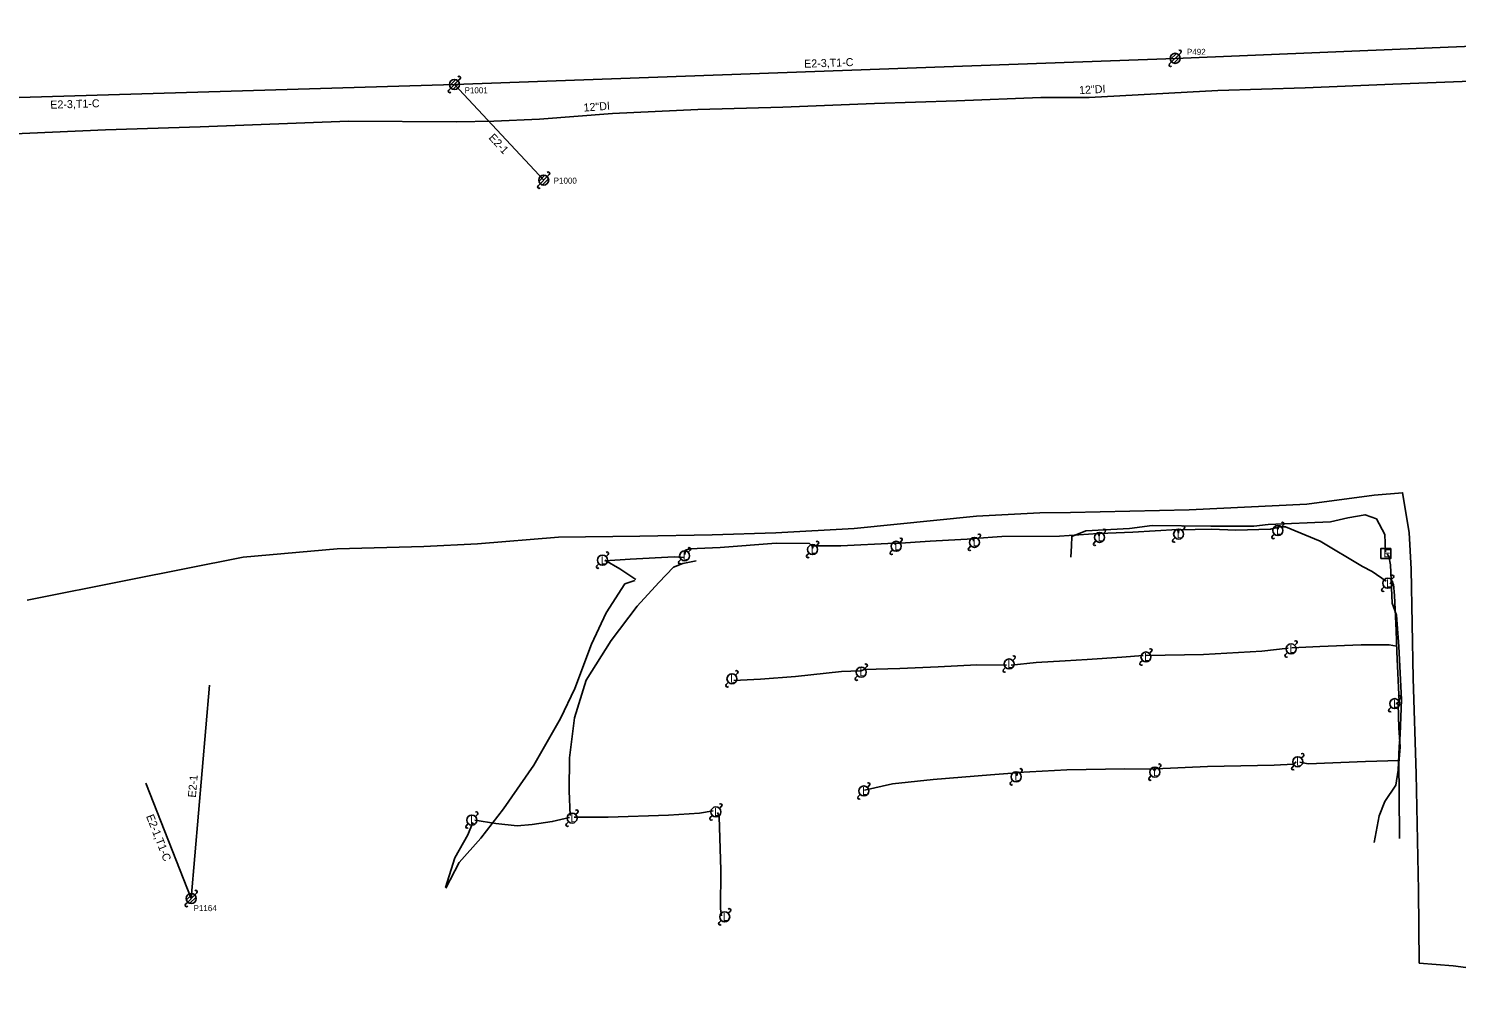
# Model space of a CAD drawing. Extents: x 1741604 to 1825760, y 1164229 to 1194908.
# Drawn here: x 1810361 to 1811075, y 1189784 to 1190261 of the extents above; entities that cross this region are included whole.
import ezdxf

# ---------------------------------------------------------------- set-up
doc = ezdxf.new("R2010")
doc.units = 0
for name, color, linetype in [('RD_EX_SU_Elec', 7, 'Continuous'), ('RD_EX_SU_Gas', 7, 'Continuous'), ('RD_EX_SU_H2O', 7, 'Continuous'), ('RD_EX_SU_Ovhd', 7, 'Continuous'), ('RD_EX_SU_Pole', 7, 'Continuous'), ('RD_EX_SU_TX_H2O', 7, 'Continuous'), ('RD_EX_SU_TX_Pole', 7, 'Continuous')]:
    doc.layers.add(name, color=color, linetype=linetype)

# ---------------------------------------------------------------- blocks, each defined once
blk = doc.blocks.new('SUE_EHH')
at = {"layer": 'RD_EX_SU_Elec'}
blk.add_lwpolyline([(2.5, 2.5), (-2.5, 2.5), (-2.5, -2.5), (2.5, -2.5)], close=True, dxfattribs=at)
blk.add_text('E', height=4, dxfattribs=at).set_placement((-1.24, -2))
blk = doc.blocks.new('SUE_PP')
at = {"layer": 'RD_EX_SU_Pole'}
for p, q in [((-2.41, -0.65), (0.65, 2.41)), ((-1.77, -1.77), (1.77, 1.77)), ((-0.65, -2.41), (2.41, 0.65)), ((1.77, 1.77), (2.83, 2.83)), ((-2.83, -2.83), (-1.77, -1.77))]:
    blk.add_line(p, q, dxfattribs=at)
blk.add_circle((0, 0), 2.5, dxfattribs=at)
for centre, start, end in [((2.3, 3.36), 315, 135), ((-2.3, -3.36), 135, 315)]:
    blk.add_arc(centre, 0.75, start, end, dxfattribs=at)

msp = doc.modelspace()

# ---------------------------------------------------------------- linework, layer by layer
at = {"layer": 'RD_EX_SU_Elec'}
for points in [[(1810882.41, 1189997.06), (1810882.6, 1190002.81), (1810882.79, 1190007.43), (1810889.9, 1190010.31), (1810911.74, 1190011.45), (1810922.99, 1190012.94), (1810952.38, 1190012.57), (1810973.77, 1190012.66), (1810980.97, 1190013.47), (1811012.08, 1190014.68), (1811020.74, 1190016.7), (1811029.44, 1190018.3), (1811035.04, 1190016.25), (1811039.36, 1190008.48), (1811039.58, 1189999.69)], [(1810833.73, 1190005.02), (1810834.03, 1190006.36), (1810847.79, 1190007.43), (1810876.65, 1190007.52), (1810896.07, 1190008.91), (1810896.52, 1190007.83)], [(1810896.57, 1190007.73), (1810896.72, 1190008.93), (1810913.32, 1190009.56), (1810935.67, 1190010.85), (1810936.1, 1190009.29)], [(1810936.21, 1190009.15), (1810936.37, 1190010.84), (1810952.6, 1190011.17), (1810964.74, 1190010.6), (1810982.14, 1190011.14), (1810985.36, 1190011.98), (1810985.69, 1190011.21)], [(1810985.78, 1190011.09), (1810986.08, 1190012.29), (1810989.7, 1190012.26), (1811006.91, 1190005.06), (1811028.2, 1189992.46), (1811032.96, 1189989.92), (1811039.97, 1189985.1)], [(1810689.38, 1189998.41), (1810689.68, 1190000.63), (1810691.68, 1190001.24), (1810707.07, 1190001.91), (1810735.1, 1190004.09), (1810751.67, 1190003.88), (1810753.03, 1190002.58), (1810753.21, 1190001.46)], [(1810753.2, 1190001.53), (1810753.49, 1190002.77), (1810767.39, 1190002.69), (1810794.23, 1190004.05), (1810794.71, 1190003.36)], [(1810794.68, 1190003.33), (1810794.77, 1190003.99), (1810812.01, 1190005.06), (1810833.53, 1190006.28), (1810833.69, 1190005.05)], [(1810632.17, 1189868.03), (1810631.62, 1189880.27), (1810631.82, 1189896.78), (1810634.23, 1189916.89), (1810640.01, 1189935.59), (1810652.51, 1189955.38), (1810665.66, 1189972.7), (1810676.35, 1189984.52), (1810683.7, 1189992.06), (1810688.45, 1189993.95), (1810695.02, 1189995.25)], [(1810649.4, 1189995.34), (1810662.04, 1189996.13), (1810684.1, 1189997.27), (1810688.66, 1189997.01)], [(1810649.5, 1189995.56), (1810656.92, 1189991.27), (1810664.99, 1189985.89)], [(1811033.97, 1189854.58), (1811036.39, 1189867.83), (1811039.22, 1189875.07), (1811044.81, 1189883.1), (1811045.89, 1189890.69), (1811046.4, 1189902.32), (1811046.89, 1189908.41), (1811047.67, 1189925.91), (1811046.34, 1189952.43), (1811045.11, 1189968.19), (1811043.03, 1189974.06), (1811042.09, 1189993.25), (1811041.27, 1189997.63), (1811040.39, 1189998.52)], [(1810569.96, 1189831.7), (1810576.53, 1189844.54), (1810587.41, 1189856.76), (1810598.7, 1189871.38), (1810614.01, 1189893.17), (1810627.25, 1189916.45), (1810634.46, 1189931.47), (1810642.82, 1189953.65), (1810650.1, 1189969.23), (1810659.48, 1189983.75), (1810664.39, 1189985.49)], [(1811041.79, 1189984.09), (1811043.67, 1189983.61), (1811044.05, 1189978), (1811045.02, 1189960.44), (1811045.24, 1189949.72), (1811046.45, 1189924.79), (1811044.89, 1189923.94)], [(1810919.94, 1189947.98), (1810948.66, 1189948.49), (1810977.79, 1189950.17), (1810991.03, 1189951.57)], [(1810992.78, 1189951.74), (1811006.88, 1189952.43), (1811027.4, 1189953.36), (1811041.44, 1189953.37), (1811045.18, 1189952.65)], [(1810777.62, 1189940.28), (1810779.09, 1189940.94), (1810796.85, 1189941.53), (1810816, 1189942.3), (1810835.36, 1189943.35), (1810850.26, 1189943.1)], [(1810852.6, 1189943.18), (1810865.04, 1189944.39), (1810879.54, 1189945.23), (1810890.47, 1189946.03), (1810907.79, 1189947.12), (1810918.52, 1189947.89)], [(1810713.88, 1189935.52), (1810727.23, 1189936.17), (1810744.67, 1189937.45), (1810767.73, 1189940.04), (1810776.98, 1189940.35)], [(1811044.79, 1189923.96), (1811045.98, 1189923.72), (1811046.3, 1189911.84), (1811046.92, 1189902.32), (1811046.36, 1189894.11), (1811046.45, 1189878.94), (1811046.66, 1189856.56)], [(1810924.21, 1189890.35), (1810924.62, 1189891.33), (1810950.58, 1189892.52), (1810983.93, 1189893.16), (1810993.65, 1189893.61), (1810994.99, 1189894.8)], [(1810996.74, 1189894.72), (1811001.02, 1189893.84), (1811029.56, 1189895.05), (1811046.45, 1189895.43)], [(1810779.27, 1189880.69), (1810793.14, 1189883.8), (1810813.55, 1189885.99), (1810842.2, 1189888.26), (1810855.13, 1189889.39), (1810855.27, 1189887.92)], [(1810855.32, 1189887.77), (1810855.68, 1189889.43), (1810880.3, 1189890.8), (1810909.26, 1189891.31), (1810923.86, 1189891.12), (1810924.01, 1189890.37)], [(1810569.7, 1189832.07), (1810574.42, 1189846.88), (1810581.01, 1189858.31), (1810583.43, 1189864.5)], [(1810584.48, 1189865.7), (1810594.86, 1189864.03), (1810605.53, 1189862.81), (1810613.03, 1189863.44), (1810623.12, 1189864.97), (1810631.84, 1189867.06)], [(1810634.12, 1189867.14), (1810651.15, 1189867.24), (1810681.2, 1189868.26), (1810696.71, 1189869.18), (1810703.59, 1189870.37)], [(1810707.76, 1189817.87), (1810707.2, 1189821.31), (1810707.42, 1189840.71), (1810706.54, 1189867.52), (1810705.68, 1189869.44)]]:
    msp.add_lwpolyline(points, dxfattribs=at)
at = {"layer": 'RD_EX_SU_Gas'}
for points in [[(1810734.82, 1190009.27), (1810773.98, 1190011.4), (1810835.13, 1190017.51), (1810866.87, 1190019.27), (1810882.2, 1190019.48), (1810941.55, 1190020.78), (1811000.3, 1190023.52), (1811033.9, 1190028.14), (1811048.12, 1190029.33), (1811051.53, 1190009.48), (1811052.43, 1189991.18), (1811053.52, 1189936.49), (1811054.97, 1189888.82), (1811056.1, 1189830.56), (1811056.46, 1189794.24), (1811073.37, 1189792.97), (1811131.67, 1189785.28), (1811150.31, 1189783.6)], [(1810360.73, 1189975.64), (1810410.81, 1189985.57), (1810468.67, 1189997.18), (1810515.69, 1190001.21), (1810558.98, 1190002.44), (1810585.76, 1190003.83), (1810626.31, 1190007.08), (1810666.92, 1190007.6), (1810703.04, 1190008.2), (1810734.82, 1190009.27)]]:
    msp.add_lwpolyline(points, dxfattribs=at)
at = {"layer": 'RD_EX_SU_H2O'}
for points in [[(1810575.17, 1190214.64), (1810594, 1190215), (1810616.7, 1190215.99), (1810653.22, 1190218.84), (1810695.85, 1190220.76), (1810738.35, 1190222.04), (1810784.17, 1190223.81), (1810825.15, 1190225.11), (1810867.29, 1190226.82), (1810891.53, 1190226.72), (1810955.86, 1190230.25), (1810999.49, 1190231.58), (1811043.25, 1190233.5), (1811086.58, 1190235.09)], [(1809591.04, 1190181.32), (1809610.39, 1190182.17), (1809696.97, 1190185.67), (1809786.87, 1190188.66), (1809883.54, 1190192.41), (1809933.92, 1190194.51), (1810049.07, 1190198.52), (1810146.27, 1190201.48), (1810237.73, 1190204.86), (1810335.34, 1190207.78), (1810399.91, 1190210.57), (1810447.22, 1190212.22), (1810521.22, 1190215.05), (1810575.17, 1190214.64)]]:
    msp.add_lwpolyline(points, dxfattribs=at)
at = {"layer": 'RD_EX_SU_Ovhd'}
for p, q in [((1810934.49, 1190246.37), (1811299.74, 1190261.25)), ((1810574.24, 1190233.31), (1810934.49, 1190246.37)), ((1810212.63, 1190222.37), (1810574.24, 1190233.31)), ((1810574.24, 1190233.31), (1810618.85, 1190185.51)), ((1810442.69, 1189826.54), (1810451.79, 1189933.09)), ((1810419.99, 1189884.17), (1810442.69, 1189826.54))]:
    msp.add_line(p, q, dxfattribs=at)
at = {"layer": 'RD_EX_SU_Pole'}
for p, q in [((1810931.66, 1190243.54), (1810932.72, 1190244.6)), ((1810932.07, 1190245.72), (1810935.13, 1190248.79)), ((1810932.72, 1190244.6), (1810936.25, 1190248.14)), ((1810933.84, 1190243.96), (1810936.9, 1190247.02)), ((1810936.25, 1190248.14), (1810937.31, 1190249.2)), ((1810571.83, 1190232.66), (1810574.89, 1190235.73)), ((1810576.01, 1190235.08), (1810577.07, 1190236.14)), ((1810571.41, 1190230.48), (1810572.47, 1190231.54)), ((1810572.47, 1190231.54), (1810576.01, 1190235.08)), ((1810573.59, 1190230.9), (1810576.65, 1190233.96)), ((1810616.43, 1190184.86), (1810619.49, 1190187.92)), ((1810617.08, 1190183.74), (1810620.61, 1190187.28)), ((1810618.2, 1190183.09), (1810621.26, 1190186.15)), ((1810620.61, 1190187.28), (1810621.67, 1190188.34)), ((1810616.02, 1190182.68), (1810617.08, 1190183.74)), ((1810835.92, 1190006.26), (1810836.98, 1190007.32)), ((1810898.46, 1190008.78), (1810899.52, 1190009.84)), ((1810933.39, 1190005.81), (1810934.45, 1190006.87)), ((1810937.98, 1190010.4), (1810939.04, 1190011.47)), ((1810983, 1190007.59), (1810984.06, 1190008.65)), ((1810987.6, 1190012.18), (1810988.66, 1190013.24)), ((1810691.09, 1189999.56), (1810692.15, 1190000.62)), ((1810755.03, 1190002.68), (1810756.09, 1190003.74)), ((1810792.23, 1189999.71), (1810793.29, 1190000.77)), ((1810796.82, 1190004.3), (1810797.88, 1190005.36)), ((1810831.32, 1190001.66), (1810832.38, 1190002.72)), ((1810893.86, 1190004.18), (1810894.92, 1190005.24)), ((1810645.42, 1189992.77), (1810646.48, 1189993.83)), ((1810650.02, 1189997.37), (1810651.08, 1189998.43)), ((1810686.49, 1189994.97), (1810687.55, 1189996.03)), ((1810750.44, 1189998.08), (1810751.5, 1189999.14)), ((1811042.5, 1189985.83), (1811043.56, 1189986.89)), ((1811037.91, 1189981.23), (1811038.97, 1189982.29)), ((1810921.66, 1189949), (1810922.72, 1189950.06)), ((1810994.2, 1189953.02), (1810995.26, 1189954.08)), ((1810853.27, 1189945.48), (1810854.33, 1189946.54)), ((1810917.06, 1189944.4), (1810918.12, 1189945.46)), ((1810989.6, 1189948.42), (1810990.66, 1189949.48)), ((1810714.74, 1189938.09), (1810715.8, 1189939.15)), ((1810774.75, 1189936.83), (1810775.81, 1189937.89)), ((1810779.35, 1189941.42), (1810780.41, 1189942.48)), ((1810848.67, 1189940.89), (1810849.73, 1189941.95)), ((1810710.15, 1189933.5), (1810711.21, 1189934.56)), ((1811041.38, 1189921.07), (1811042.44, 1189922.13)), ((1811045.98, 1189925.66), (1811047.04, 1189926.72)), ((1810992.94, 1189892.05), (1810994, 1189893.11)), ((1810997.54, 1189896.65), (1810998.6, 1189897.71)), ((1810852.18, 1189884.51), (1810853.24, 1189885.57)), ((1810856.77, 1189889.11), (1810857.83, 1189890.17)), ((1810921.5, 1189886.86), (1810922.56, 1189887.92)), ((1810926.09, 1189891.45), (1810927.15, 1189892.51)), ((1810776.05, 1189877.43), (1810777.11, 1189878.49)), ((1810780.64, 1189882.03), (1810781.7, 1189883.09)), ((1810706.71, 1189871.58), (1810707.77, 1189872.64)), ((1810584.7, 1189867.49), (1810585.76, 1189868.55)), ((1810630.22, 1189863.87), (1810631.28, 1189864.93)), ((1810634.81, 1189868.47), (1810635.88, 1189869.53)), ((1810702.12, 1189866.98), (1810703.18, 1189868.04)), ((1810580.1, 1189862.89), (1810581.16, 1189863.95)), ((1810706.49, 1189814.54), (1810707.55, 1189815.6)), ((1810711.08, 1189819.14), (1810712.15, 1189820.2))]:
    msp.add_line(p, q, dxfattribs=at)
for centre in [(1810934.49, 1190246.37), (1810574.24, 1190233.31), (1810618.85, 1190185.51), (1810834.15, 1190004.49), (1810896.69, 1190007.01), (1810936.22, 1190008.64), (1810985.83, 1190010.41), (1810689.32, 1189997.8), (1810753.26, 1190000.91), (1810795.05, 1190002.54), (1810648.25, 1189995.6), (1811040.74, 1189984.06), (1810919.89, 1189947.23), (1810992.43, 1189951.25), (1810851.5, 1189943.72), (1810712.98, 1189936.33), (1810777.58, 1189939.65), (1811044.21, 1189923.9), (1810995.77, 1189894.88), (1810855, 1189887.34), (1810924.33, 1189889.69), (1810778.88, 1189880.26), (1810704.95, 1189869.81), (1810582.93, 1189865.72), (1810633.05, 1189866.7), (1810709.32, 1189817.37)]:
    msp.add_circle(centre, 2.5, dxfattribs=at)
for centre, start, end in [((1810936.78, 1190249.73), 315, 135), ((1810932.19, 1190243.01), 135, 315), ((1810576.54, 1190236.67), 315, 135), ((1810571.94, 1190229.95), 135, 315), ((1810621.14, 1190188.87), 315, 135), ((1810616.55, 1190182.15), 135, 315), ((1810988.13, 1190013.77), 315, 135), ((1810836.45, 1190007.85), 315, 135), ((1810898.99, 1190010.37), 315, 135), ((1810938.51, 1190012), 315, 135), ((1810983.53, 1190007.06), 135, 315), ((1810650.55, 1189998.96), 315, 135), ((1810691.62, 1190001.15), 315, 135), ((1810755.56, 1190004.27), 315, 135), ((1810792.76, 1189999.18), 135, 315), ((1810797.35, 1190005.89), 315, 135), ((1810831.85, 1190001.13), 135, 315), ((1810894.39, 1190003.65), 135, 315), ((1810933.92, 1190005.28), 135, 315), ((1810645.95, 1189992.24), 135, 315), ((1810687.02, 1189994.44), 135, 315), ((1810750.97, 1189997.55), 135, 315), ((1811043.03, 1189987.42), 315, 135), ((1811038.44, 1189980.7), 135, 315), ((1810922.19, 1189950.59), 315, 135), ((1810994.73, 1189954.61), 315, 135), ((1810779.88, 1189943.01), 315, 135), ((1810853.8, 1189947.07), 315, 135), ((1810917.59, 1189943.87), 135, 315), ((1810990.13, 1189947.89), 135, 315), ((1810715.27, 1189939.68), 315, 135), ((1810775.28, 1189936.3), 135, 315), ((1810849.2, 1189940.36), 135, 315), ((1810710.68, 1189932.97), 135, 315), ((1811046.51, 1189927.25), 315, 135), ((1811041.91, 1189920.54), 135, 315), ((1810926.62, 1189893.04), 315, 135), ((1810998.07, 1189898.24), 315, 135), ((1810857.3, 1189890.7), 315, 135), ((1810922.03, 1189886.33), 135, 315), ((1810993.47, 1189891.52), 135, 315), ((1810781.17, 1189883.62), 315, 135), ((1810852.71, 1189883.98), 135, 315), ((1810707.24, 1189873.17), 315, 135), ((1810776.58, 1189876.9), 135, 315), ((1810585.23, 1189869.08), 315, 135), ((1810635.35, 1189870.06), 315, 135), ((1810702.65, 1189866.45), 135, 315), ((1810580.63, 1189862.36), 135, 315), ((1810630.75, 1189863.34), 135, 315), ((1810711.62, 1189820.73), 315, 135), ((1810707.02, 1189814.01), 135, 315)]:
    msp.add_arc(centre, 0.75, start, end, dxfattribs=at)

# ---------------------------------------------------------------- block references
at = {"layer": 'RD_EX_SU_Elec'}
msp.add_blockref('SUE_EHH', (1811039.8, 1189999), dxfattribs=at)
at = {"layer": 'RD_EX_SU_Pole'}
msp.add_blockref('SUE_PP', (1810442.69, 1189826.54), dxfattribs=at)

# ---------------------------------------------------------------- texts
at = {"layer": 'RD_EX_SU_Ovhd'}
for s, rotation, p in [('E2-3,T1-C', 2.07631, (1810749.1, 1190241.65)), ('E2-3,T1-C', 1.73268, (1810372.29, 1190221.2)), ('E2-1', 313.01831, (1810591.09, 1190206.46)), ('E2-1', 85.11711, (1810444.98, 1189876.84)), ('E2-1,T1-C', 291.49399, (1810420.05, 1189867.65))]:
    msp.add_text(s, height=4, rotation=rotation, dxfattribs=at).set_placement(p)
at = {"layer": 'RD_EX_SU_Pole'}
for p in [(1810895.83, 1190005.01), (1810935.35, 1190006.64), (1810984.97, 1190008.41), (1810688.46, 1189995.8), (1810752.4, 1189998.91), (1810794.19, 1190000.54), (1810833.29, 1190002.49), (1810647.39, 1189993.6), (1811039.87, 1189982.06), (1810991.57, 1189949.25), (1810850.64, 1189941.72), (1810919.03, 1189945.23), (1810712.11, 1189934.33), (1810776.72, 1189937.65), (1811043.35, 1189921.9), (1810994.91, 1189892.88), (1810854.14, 1189885.34), (1810923.46, 1189887.69), (1810778.01, 1189878.26), (1810704.08, 1189867.81), (1810582.07, 1189863.72), (1810632.18, 1189864.7), (1810708.45, 1189815.37)]:
    msp.add_text('L', height=4, dxfattribs=at).set_placement(p)
at = {"layer": 'RD_EX_SU_TX_H2O'}
for rotation, p in [(3.13882, (1810886.56, 1190228.45)), (4.4549, (1810638.94, 1190219.73))]:
    msp.add_text('12"DI', height=4, rotation=rotation, dxfattribs=at).set_placement(p)
at = {"layer": 'RD_EX_SU_TX_Pole'}
for s, p in [('P492', (1810940.38, 1190248.12)), ('P1001', (1810579.31, 1190228.91)), ('P1000', (1810623.84, 1190183.76)), ('P1164', (1810443.86, 1189820.22))]:
    msp.add_text(s, height=3, dxfattribs=at).set_placement(p)

doc.saveas('drawing.dxf')
